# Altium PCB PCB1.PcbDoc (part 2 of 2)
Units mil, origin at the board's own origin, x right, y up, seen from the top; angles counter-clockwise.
Board outline 3937.01 x 3937.01 mil, 4 copper layers (Top Layer, Layer 1, Layer 2, Bottom Layer), stack 68.734 mil thick; 96 components, 71 nets, 353 pads, 281 vias.
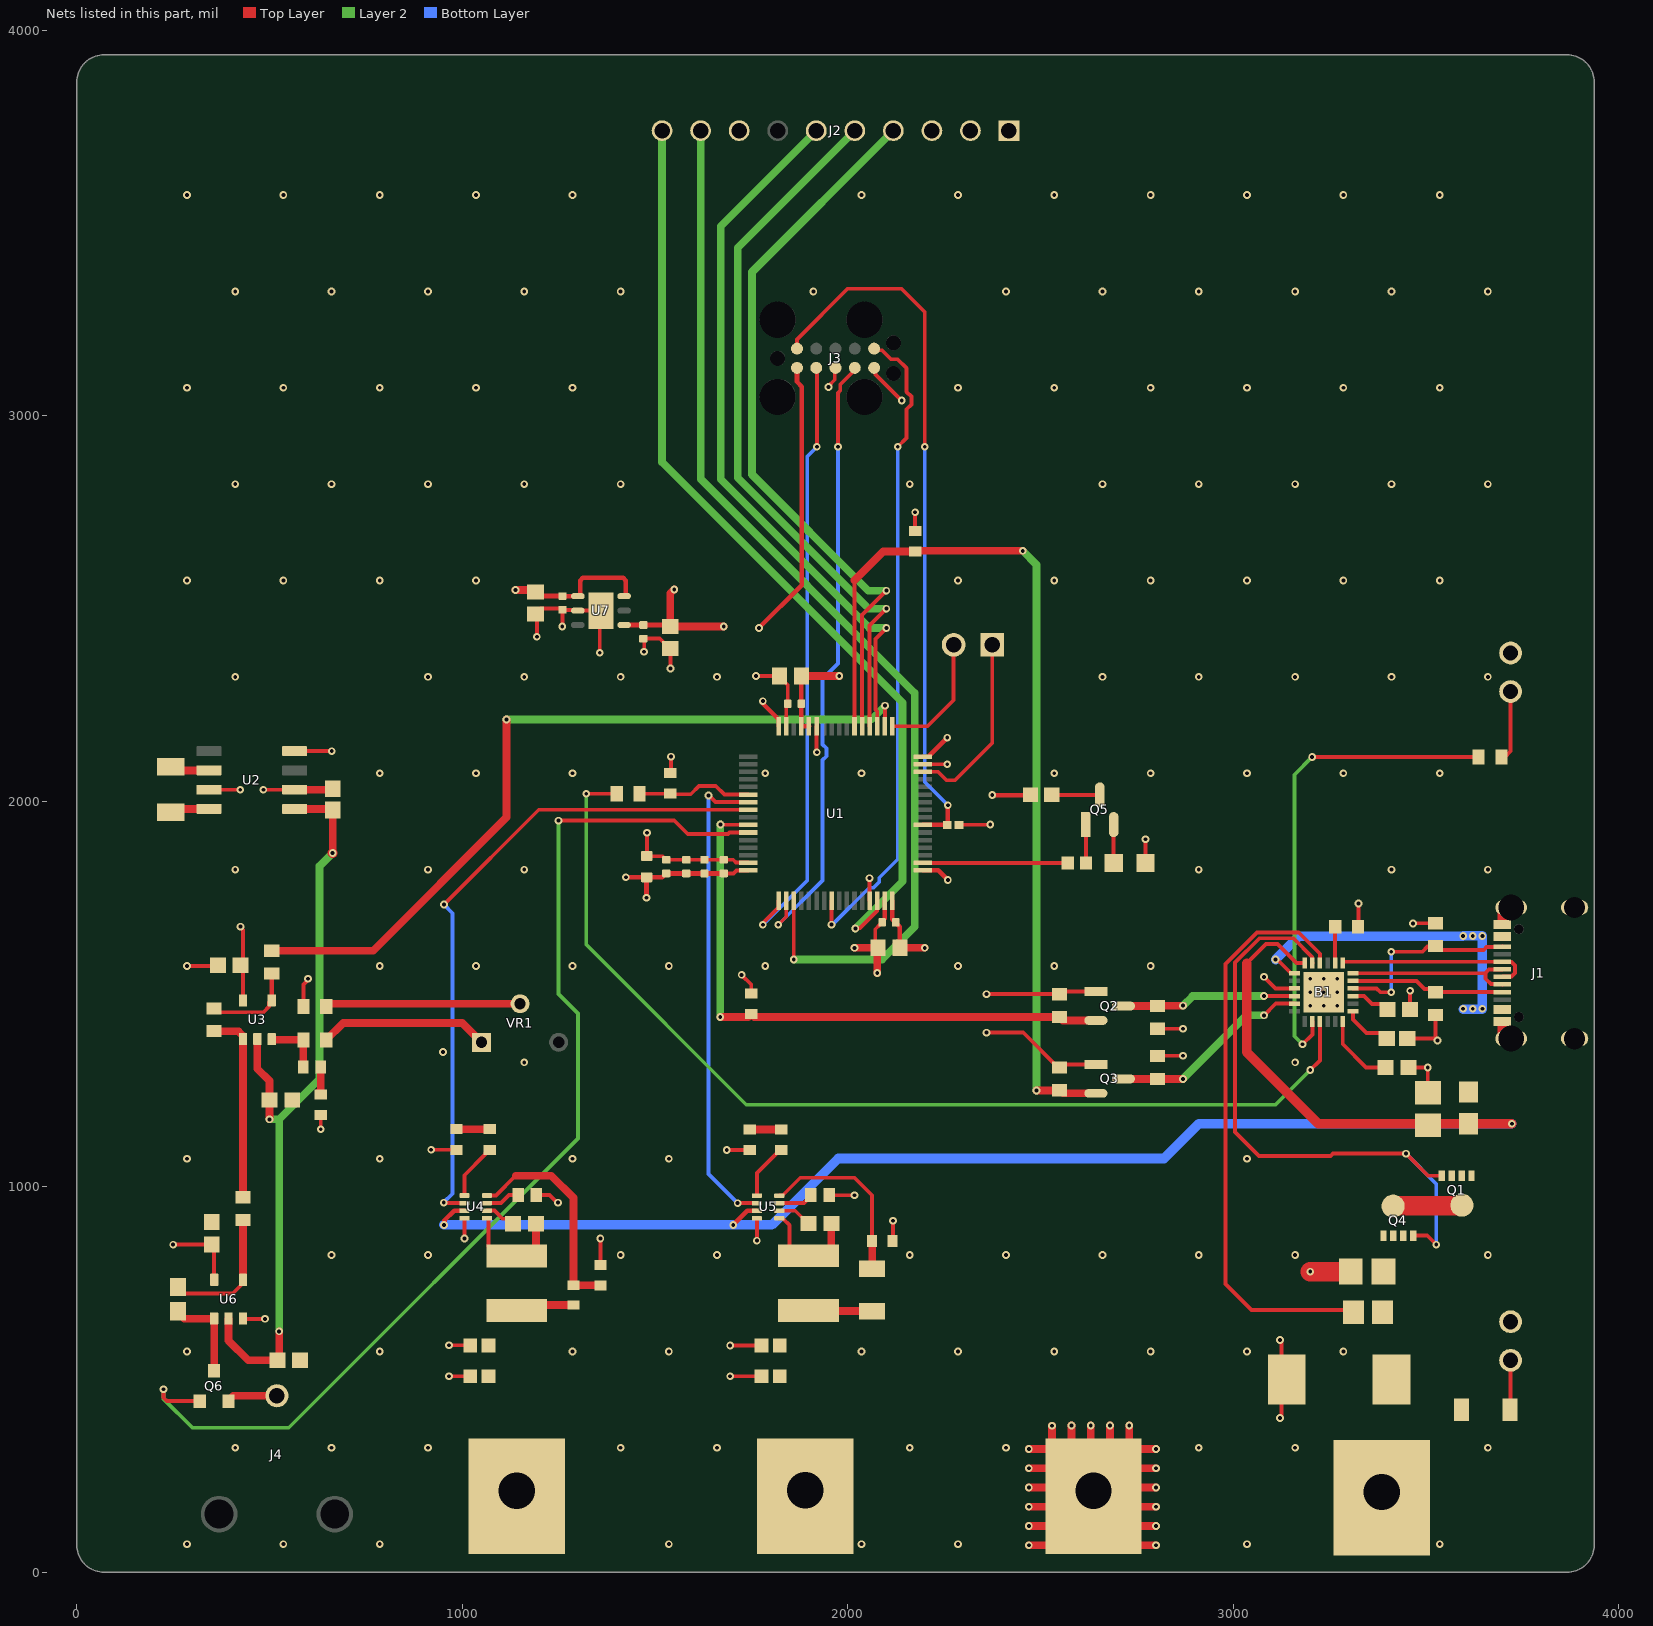
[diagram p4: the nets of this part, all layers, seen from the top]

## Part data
B1: library part CMP-019-00051-3, "USB, Type-C Controller PMIC W-QFN4040-24 (Type A1)", Manufacturer_Name="Diodes Incorporated", Manufacturer_Part_Number=AP33772SDKZ-13-FA01, Mouser Part Number=621-P33772SDKZ13FA01
C1 C4 C17 C19 C22 C23 C24 C27: library part CMP-2006-02299-1, "C0603C104K4RAC7013", Manufacturer=Kemet
C2 C14 C30 C33: library part CMP-001-00004-6, "Chip Capacitor, 1 uF, +/- 10%, 16 V, 0603 (1608 Metric)", Capacitor Type=Ceramic, Case/Package=0603, Max Operating Temperature=125°C, Min Operating Temperature=-55°C, Tolerance=10%, Voltage Rating=16V
C3 C8 C9 C10 C11 C13 C31 C32: library part CMP-001-00061-3, "Chip Capacitor, 100nF +/-20%, 10V, 0402, Thickness 0.6 mm", Case/Package=0402, Max Operating Temperature=85°C, Min Operating Temperature=-55°C, Tolerance=20%, Voltage Rating=10V
C5: library part CMP-03422-000857-1, "CC0603MRX5R8BB105 / CAP CER 1UF 25V X5R 0603", Capacitance="1 uF", Manufacturer=YAGEO, Manufacturer Part Number=CC0603MRX5R8BB105, Package=CC0603-DA, Temperature="-55°C to +125°C", Temperature Characteristic=X5R, Temperature Coefficient=15%, Temperature Range High=+125°C, Temperature Range Low=-55°C, Tolerance=0.2, Voltage="25 V"
C6: library part CMP-001-00001-6, "Chip Capacitor, 0.1 uF, +/- 5%, 16 V, 0402 (1005 Metric)", Capacitor Type=Ceramic, Case/Package=0402, Max Operating Temperature=125°C, Min Operating Temperature=-55°C, Tolerance=5%, Voltage Rating=16V
C7: library part CMP-001-00076-4, "Chip Capacitor, 4.7µF +/-20%, 10V, 0603, Thickness 1 mm", Case/Package=0603, Max Operating Temperature=85°C, Min Operating Temperature=-55°C, Tolerance=10%, Voltage Rating=10V
C12 C15: library part CMP-2000-06047-2, "C3216X7R1V106K160AC / Multilayer Ceramic Capacitors 10uF ±10% 35V X7R SMD 1206", Case Code (Imperial)=1206, Case Code (Metric)=3216, Dielectric=X7R, Dielectric Material=Ceramic, Max Operating Temperature=125°C, Min Operating Temperature=-55°C, Package Quantity=2000, Tolerance=10%, Voltage Rating=35V
C16: library part CMP-1037-05002-1, "CAP 47uF 10V ±20% 1206 (3216 Metric) Thickness 1.9mm SMD", Case-EIA=1206, Case-Metric=3216, Rated Voltage="10 V", Tolerance=Â±20%
C18: library part CMP-06035-020296-1, "Chip Multilayer Ceramic Capacitors for General Purpose, 0603, 10uF, X7R, 15%, 10%, 10V / GRM188Z71A106KA73J"
C20 C21: library part CMP-03020-034693-1, "C0603C333J4REC7411 / CAP CER 0603 33NF 16V X7R 5%", Case/Package=0603, Max Operating Temperature=125°C, Min Operating Temperature=-55°C, Tolerance=5%, Voltage Rating=16V
C25 C26 C28 C29: library part CMP-2000-06337-3, "GRM188R61A226ME15D / Chip Multilayer Ceramic Capacitors for General Purpose, 0603, 22uF, X5R, 15%, 20%, 10V", Case Code (Imperial)=0603, Case Code (Metric)=1608, Dielectric=X5R, Max Operating Temperature=85°C, Min Operating Temperature=-55°C, Package Quantity=4000, Tolerance=20%, Voltage Rating=10V
D1: library part CMP-004-00031-2, "151051BS04000 / Single Color LED, Blue, Diffused, T-1 3/4, 4.9mm", Case/Package=Radial, Color=Blue, Forward Current=100mA, Forward Voltage=3.2V, Max Operating Temperature=85°C, Max Reverse Voltage (DC)=5V, Min Operating Temperature=-40°C, Test Current=20mA
D2: library part CMP-007-00039-1, "151051RS11000 / WL-TMRC Red Color Diffused 5 mm Round Through Hole LED", Case/Package=Radial, Forward Current=100mA, Forward Voltage=2.1V, Max Operating Temperature=85°C, Min Operating Temperature=-40°C
D3: library part CMP-2000-05906-2, "DIODE SCHOTTKY 50V 5A SMC", Average Rectified Current=5A, Capacitance=300pF, Case/Package=SMC, Forward Voltage=700mV, Max Forward Surge Current (Ifsm)=100A, Max Operating Temperature=125°C, Max Repetitive Reverse Voltage (Vrrm)=50V, Min Operating Temperature=-55°C, Package Quantity=3000, Peak Reverse Current=500uA
D4: library part CMP-2000-06620-1, "Ultra Bright AlInGaP Chip LED, 75 mW, -55 to 85 degC, 2-Pin SMD (0805), RoHS, Tape and Reel", Emitting Color=YellowGreen, Forward Current=30mA, Forward Voltage=2.4V, Manufacturer=Lite-On, Operating Temp Range=-55Cto85C, Operating Temperature Classification=Industrial, Package Description="2-Pin Surface Mounted Device, Body 2 x 1.25 mm", Package Reference=LTST-C170KGKT-2, Package Type=ChipLed, Power Dissipation=75W, Power Dissipation Max=75mW, Reverse Voltage=5V, Test Current (It)=20mA
J1: library part CMP-245163-000001-1, "CONN RCPT USB2.0 TYPEC 5A", Current Rating=5/6.25/1.25/0.25A, Manufacturer=GCT, Package=0, Temperature="-40°C to +85°C", Temperature Range High=+85°C, Temperature Range Low=-40°C, Voltage Rating=20V
J2: library part CMP-039-000000-3, "Samtec Connector .1\" pitch, long ahh pins", Package=None
J3: library part CMP-035-000000-1, "Cbl Plug-Of-Nails 10-Pin w/Legs", Package=None
J4: library part CMP-002-00084-4, "JACK, BNC, 50OHM, R/A, THT; Connector Type: BNC Coaxial; Body Style: Right Angle J", Case/Package=None
J5 J6 J7 J8: library part CMP-002-00082-3, "Banana Test Connector, 4mm, Jack, Panel Mount, 15 A, 7 kV, Tin Plated Contacts, Red", Max Current Rating=15A, Max Operating Temperature=85°C, Min Operating Temperature=-55°C, Voltage Rating=3.5kV
J9: library part CMP-15831-000009-1, "CONN HEADER VERT 2POS 2.54MM", Current Rating=3A, Manufacturer=Harwin, Temperature="-40°C to +105°C", Temperature Range High=+105°C, Temperature Range Low=-40°C
L1 L2: library part CMP-14484-001090-1, "NRS5040T3R3NMGJ / SMD Power Inductors 3.3uH ±30% 3.3A 35.1mΩ", Case/Package=Nonstandard, Current Rating=3.3A, DC Resistance (DCR)=27mR, Max Operating Temperature=120°C, Min Operating Temperature=-25°C, Resistor Type=Wirewound, Saturation Current=4A, Self Resonant Frequency=32MHz, Test Frequency=100kHz, Tolerance=30%
Q1 Q4: library part CMP-12801-000078-1, "MOSFET N-CH 60V 13A POWERDI", Capacitance=2.09E-09F, Continuous Drain Current (ID)=30A, Drain to Source Breakdown Voltage=60V, Drain to Source Resistance=7.8mR, Gate to Source Voltage (Vgs)=20V, Input Capacitance=2.09nF, Max Operating Temperature=150°C, Max Power Dissipation=2.2W, Min Operating Temperature=-55°C, Package Quantity=2000
Q2 Q3: library part CMP-07173-000101-1, "MOSFET N-CH 50V 220MA SOT-23", Case/Package=SOT-23, Continuous Drain Current (ID)=220mA, Drain to Source Breakdown Voltage=50V, Drain to Source Resistance=3.5R, Gate to Source Voltage (Vgs)=20V, Input Capacitance=27pF, Max Operating Temperature=150°C, Max Power Dissipation=360mW, Min Operating Temperature=-55°C, On-State Resistance=6R, Package Quantity=1, Threshold Voltage=1.3V
Q5: library part CMP-2000-04931-2, "TRANS NPN 40V 0.2A SMD SOT23-3", Case/Package=SOT-23, Collector Base Voltage (VCBO)=60V, Collector Emitter Breakdown Voltage=40V, Collector Emitter Saturation Voltage=300mV, Continuous Collector Current=200mA, Emitter Base Voltage (VEBO)=6V, Frequency=300MHz, Max Operating Temperature=150°C, Max Power Dissipation=300mW, Min Operating Temperature=-55°C, Package Quantity=3000, Power Dissipation=350mW
Q6: library part CMP-1048-00772-1, "General Purpose Transistor, NPN Silicon, 3-Pin SOT-23, Pb-Free, Tape and Reel", Manufacturer="On Semiconductor"
R1 R2 R4 R5 R7 R8 R10: library part CMP-2000-04091-1, "RC0603FR-075K1L", Manufacturer=Yageo
R3 R13 R14 R15 R16 R23: library part CMP-009-00014-5, "Chip Resistor, 1 KOhm, +/-1%, 0.1 W, -55 to 155 degC, 0603 (1608 Metric)", Case/Package=0603, Max Operating Temperature=155°C, Min Operating Temperature=-55°C, Power=100mW, Tolerance=1%, Voltage Rating=50V
R6: library part CMP-06022-000566-1, "NCG18XH103F0SRB / NTC Thermistor 10kΩ 1% SMD  0201 (0603 Metric)", Case/Package=0603, Max Operating Temperature=150°C, Min Operating Temperature=-55°C, Tolerance=1%
R9 R18 R19 R20 R21 R22 R24 R27 R32 R33: library part CMP-2100-03664-2, "RC0603FR-0710KL / RES 10K OHM 1% 1/10W 0603", Case Code (Imperial)=0603, Case Code (Metric)=1608, Max Operating Temperature=155°C, Max Power Dissipation=100mW, Min Operating Temperature=-55°C, Resistance=10kR, Resistance Tolerance=1%, Resistor Type="Thick Film", Temperature Coefficient=100ppm/°C, Voltage Rating=75V, Voltage Rating (DC)=50V
R11: library part CMP-009-00179-1, "5 mOhms Â±1% 0.5W, 1/2W Chip Resistor 0805 (2012 Metric) Automotive AEC-Q200, Current Sense Thick Film", Case/Package="2012-2 Panasonic"
R12: library part CMP-2001-00580-1, "ERA6AEB101V", Manufacturer=Panasonic
R17: library part CMP-2000-03826-1, "CRCW0603100RFKTA", Manufacturer="Vishay Dale"
R25: library part CMP-03412-001731-1, "RT1206BRD075KL / RES SMD 5K OHM 0.1% 1/4W 1206", Manufacturer=Yageo, Manufacturer Part Number=RT1206BRD075KL, Package=RT1206-0.65, Power Rating=0.25W, Resistance=5kΩ, Temperature="-55°C to +155°C", Temperature Coefficient=25ppm/°C, Temperature Range High=+155°C, Temperature Range Low=-55°C, Tolerance=0.1%, Voltage Rating=200V
R26: library part CMP-250906-096381-1, "RES Thin Film, 31.2kΩ, 0.1%, 0.25W, 50ppm/°C, 1206"
R28: library part CMP-26527-007404-1, "RMCF0603JG3K00 / 3kΩ ±5% 0.1W 0603 Thick Film Chip Resistor AEC-Q200 compliant", Case/Package=0603, Max Operating Temperature=155°C, Max Power Dissipation=100mW, Min Operating Temperature=-55°C, Resistance=3kR, Resistor Type="Thick Film", Temperature Coefficient=200ppm/°C, Tolerance=5%
R29: library part CMP-1012-00705-2, "RC0603FR-0752K3L", Manufacturer=Yageo
R30: library part CMP-26527-005064-1, "RMCF0603JG510R / 510Ω ±5% 0.1W 0603 Thick Film Chip Resistor AEC-Q200 compliant", Case/Package=0603, Max Operating Temperature=155°C, Max Power Dissipation=100mW, Min Operating Temperature=-55°C, Package Quantity=10000, Resistor Type="Thick Film", Temperature Coefficient=200ppm/°C, Tolerance=5%
R31: library part CMP-26527-003372-1, "RMCF0603FG2K00 / 2kΩ ±1% 0.1W 0603 Thick Film Chip Resistor AEC-Q200 compliant", Case/Package=0603, Max Operating Temperature=155°C, Min Operating Temperature=-55°C, Resistance=2kR, Resistor Type="Thick Film", Temperature Coefficient=100ppm/°C, Tolerance=1%
U1: library part CMP-12105-000051-1, "MAINSTREAM ARM CORTEX-M4 CORE WI", Ambient Temperature Range High=+85°C, Ambient Temperature Range Low=-40°C, Frequency=170MHz, Manufacturer=STMicroelectronics, Max Junction Temp=+105°C, Max Supply Voltage=3.6V, Min Supply Voltage=1.71V, Package=LQFP64-5W, Temperature="-40°C to +105°C"
U2: library part CMP-0065-00039-3, "Switched Capacitor Voltage Converter, 8-pin Narrow SOIC, Pb-Free", Manufacturer="Texas Instruments", PackageTopMarking=NSZXTT*LM26*63M, PowerWise=N
U3 U6: library part CMP-0272-04163-2, "Precision, Rail-to-Rail Input/Output, Low Offset Voltage, Low Input Bias Current Op Amp with E-trim, 4.5 to 36 V, -40 to 125 degC, 5-Pin SOT-23 (DBV), Green (RoHS & no Sb/Br), Tape and Reel", Temperature Max="125 degC", Temperature Min="-40 degC"
U4 U5: library part CMP-04918-000610-1, "3.8-V to 30-V, 3-A, 200-kHz to 2.2-MHz, low-IQ synchronous buck converter in SOT-583 package 8-SOT-5X3 -40 to 150"
U7: library part CMP-019-00050-2, "500 mA low quiescent current low noise voltage regulator", Case/Package="DFN EP", Dropout Voltage=400mV, Max Operating Temperature=125°C, Max Supply Voltage=5.5V, Min Operating Temperature=-40°C, Output Current=500mA, Output Voltage=3.3V
VR1: library part CMP-1747-00004-1, "Square Trimpot(R) Trimming Potentiometer, 10 KOhm, 300 V, -55 to 125 degC, 3-Pin THD, RoHS, Tube", Case Code (Imperial)=0612, Case Code (Metric)=1632, Case/Package=1206, Max Operating Temperature=125degC, Min Operating Temperature=-25degC, Package Quantity=5000, Power Rating="1 W", Resistance="50 mohm", Tolerance=1%, Voltage Rating="220 mV"

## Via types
v1: diameter 20, hole 10, Top Layer to Bottom Layer, 277 vias
v2: diameter 118.11, hole 94.49, Top Layer to Bottom Layer, 4 vias

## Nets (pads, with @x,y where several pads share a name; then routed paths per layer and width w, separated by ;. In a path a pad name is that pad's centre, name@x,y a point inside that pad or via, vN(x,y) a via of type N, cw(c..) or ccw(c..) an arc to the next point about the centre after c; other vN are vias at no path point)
3V3: C2.2 C3.2 C7.2 C8.2 C9.2 C10.2 C11.2 C13.2 C14.2 C32.2 C33.2 J3.1 Q2.1 Q3.1 R4.2 R8.2 R30.2 R32.1 R33.1 U1.1 U1.16 U1.28 U1.29 U1.32 U1.48 U1.64 U7.4 | length 2962.2
  Top Layer w10: C11.2@1678.5,1812.99 1704.09,1812.99 1711.68,1820.58 1741.83,1820.58 U1.48@1742.13,1820.87 ; v1(1725,1550) 1750,1525 R33.1@1750,1501.64 ; R32.1@2175,2701.64 v1(2175,2750) ; v1(2360,1400) 2455.59,1400 2546.06,1309.53 R8.2@2550,1309.53 ; v1(2360,1500) 2549.53,1500 R4.2@2550,1499.53 2556.93,1506.46 Q2.1@2643.85,1506.46 ; R8.2@2551.57,1309.53 2559.44,1317.4 Q3.1@2643.85,1317.4
  Top Layer w12: U7.4@1416.1,2457.6 1469.88,2457.6 C32.2@1470,2457.72 1535.83,2457.72 C33.2@1540,2453.54 ; v1(1424.48,1803.15) C7.2@1478.51,1803.15 ; v1(1477.87,1750) 1478.19,1750.32 1478.19,1802.83 C7.2@1478.51,1803.15 ; C11.2@1678.5,1812.99 C10.2@1628.5,1812.99 C9.2@1581.34,1812.99 C8.2@1529.49,1812.99 1528.5,1812.99 1518.66,1803.15 C7.2@1478.51,1803.15 ; v1(1770,2450) 1881.25,2561.25 1881.25,3075.6 1868.5,3088.35 J3.1@1868.5,3115 ; v1(1780,2260) 1781.53,2258.47 1781.53,2251.75 1820.87,2212.41 U1.32@1820.87,2194.88 ; U1.29@1879.83,2194.79 U1.29@1879.92,2194.88 ; C2.2@1879.92,2325.49 C3.2@1879.92,2253.38 U1.29@1879.92,2194.88 ; U1.28@1899.61,2194.88 U1.29@1879.92,2194.88 ; U1.64@2116.14,1742.13 2116.14,1694.65 C13.2@2124.73,1686.06 2124.73,1685.08 2135.56,1674.25 C14.2@2135.56,1620 ; U1.1@2194.88,1820.87 2235.39,1820.87 v1(2260,1796.26) ; U1.16@2194.88,2116.14 2212.41,2116.14 2212.5,2116.24 2212.5,2119.35 v1(2258.5,2165.35) ; v1(2375,2016.36) 2473.67,2016.36 R30.2@2474.11,2016.8
  Top Layer w20: v1(1550,2550) 1540,2540 C33.2@1540,2453.54 1678.19,2453.54 v1(1678.35,2453.7) ; C2.2@1879.92,2325.49 v1(1978.19,2325.49) ; C14.2@2135.56,1620 v1(2200,1620)
3VO_JACK: C26.1 C29.1 J5.1 L1.2 R26.2 | length 165.9
  Top Layer w20: L1.2@1898.58,679.22 1899.69,678.12 2062.44,678.12 R26.2@2063.54,677.02
  other v2: 1889.76,212.27
5VO: C25.1 C28.1 J6.1 L2.2 R29.2 | length 152.2
  Top Layer w20: L2.2@1142.24,679.71 1155.94,693.41 R29.2@1288.73,693.41
  other v2: 1141.73,211.85
5VO_EN: U1.40 U4.2 | length 1738
  Top Layer w10: v1(951.88,959) 952.46,958.42 1005.02,958.42 U4.2@1005.6,957.84 ; v1(952.46,1732.28) 1198.52,1978.35 U1.40@1742.13,1978.35
  Bottom Layer w10: v1(951.88,959) 975,982.12 975,1709.74 v1(952.46,1732.28)
+5: C17.2 C19.2 C30.2 C31.2 J2.02 R5.2 R7.2 R18.1 U2.8 U3.5 U6.5 U7.1 U7.6 | length 1029.4
  Top Layer w10: v1(250,850) C19.2@350,850 356.3,843.7 U6.5@356.3,758.86 ; v1(425,1675) 425,1672.29 431.1,1666.19 U3.5@431.1,1483.74 ; U2.8@565.36,2130.35 v1(661.55,2130.35) ; v1(632.79,1149.41) R18.1@632.79,1186.9 ; R7.2@2803.85,1339.06 2804.8,1340 v1(2870,1340) ; R5.2@2803.85,1410 v1(2870,1410)
  Top Layer w12: C30.2@1193.56,2548.27 1193.56,2544.81 1205.65,2532.72 C31.2@1260,2532.72 ; C31.2@1260.32,2532.4 U7.1@1299.96,2532.4 1304.09,2532.4 1305.82,2534.13 1305.82,2572.93 1312.85,2579.96 1417.45,2579.96 1424.48,2572.93 1424.48,2538.02 U7.6@1425.06,2537.44
  Top Layer w20: v1(1138.19,2548.27) C30.2@1193.56,2548.27
-5: C18.1 C24.2 C27.2 U2.5 U3.2 U6.2 | length 2037.8
  Top Layer w10: U3.2@468.5,1378.42 U3.2@468.5,1383.34
  Top Layer w20: U6.2@393.7,657.48 393.7,601.1 444.8,550 C27.2@520.47,550 525,554.53 v1(525,625) ; U3.2@468.5,1378.42 468.5,1306.5 500,1275 C24.2@500,1225 v1(500,1175) ; U2.5@565.36,1980.35 C18.1@661.55,1980.35 ; v1@664.14,1866.56 C18.1@664.14,1977.77
  Top Layer w25.59: C18.1@661.55,1980.35 C18.1@664.14,1977.77 ; v1(663.72,1866.14) v1@664.14,1866.56
  Layer 2 w20: v1(500,1175) 525,1175 ; v1(525,625) 525,1175 ; v1(663.72,1866.14) 629.96,1832.38 629.96,1279.96 525,1175
BST: C23.1 U4.6 | length 82.9
  Top Layer w10: U4.6@1063.95,938.29 1083.46,938.29 1104.4,917.35 1119.37,917.35 C23.1@1132.67,904.04
CC1: B1.17 J1.A5 R2.2 | length 399.9
  Top Layer w10: B1.17@3310.94,1534.37 3475.63,1534.37 3496.83,1513.17 3517.31,1513.17 3525.16,1505.31 J1.A5@3698.82,1505.31
CC2: B1.16 J1.B5 R1.2 | length 510.3
  Top Layer w10: B1.16@3310.94,1514.69 3372.14,1514.69 3381.98,1504.84 v1(3410.16,1504.84) ; v1(3410.16,1609.84) 3491.17,1609.84 3504.75,1623.43 R1.2@3525.16,1623.43 ; R1.2@3525.16,1624.84 3535.16,1614.84 3650.16,1614.84 3657.83,1622.52 3697.91,1622.52 J1.B5@3698.82,1623.43
  Bottom Layer w10: v1(3410.16,1504.84) v1(3410.16,1609.84)
D+: B1.19 J1.A6 J1.B6 | length 510.7
  Top Layer w10: B1.19@3284.37,1580.63 3284.37,1583.15 3285.28,1584.06 J1.B6@3698.82,1584.06 3699.73,1583.15 3722.73,1583.15 3731.46,1574.42 3731.46,1554.32 3722.73,1545.59 3699.73,1545.59 J1.A6@3698.82,1544.69
D-: B1.18 J1.A7 J1.B7 | length 456.8
  Top Layer w10: B1.18@3310.94,1554.06 3655.13,1554.06 ; J1.B7@3698.82,1525 3697.91,1525.91 3669.17,1525.91 3655.13,1539.95 3655.13,1555.22 3663.38,1563.47 3697.91,1563.47 J1.A7@3698.82,1564.37
DAC1_OUT1: R13.2 U1.18 | length 2057
  Top Layer w10: U1.18@2096.46,2194.88 2096.77,2195.2 2096.77,2248.06 v1(2097.09,2248.38)
  Top Layer w20: R13.2@505.91,1612.6 768.95,1612.6 1114.86,1958.51 v1(1114.86,2212.41)
  Layer 2 w20: v1(1114.86,2212.41) 2060.22,2212.41 2061.28,2213.47 2062.18,2213.47 v1(2097.09,2248.38)
GND: B1.3 B1.25 C1.2 C2.1 C3.1 C4.1 C5.2 C6.1 C7.1 C8.1 C9.1 C10.1 C11.1 C12.2 C13.1 C14.1 C15.2 C17.1 C18.2 C19.1 C20.2 C21.2 C24.1 C25.2 C26.2 C27.1 C28.2 C29.2 C30.1 C31.1 C32.1 C33.1 D1.2 D2.2 D3.2 D4.1 J1.1 J1.2 J1.3 J1.4 J1.A1-B12 J1.B1-A12 J2.01 J2.03 J2.08 J3.3 J3.5 J7.1 R1.1 R2.1 R6.1 R9.2 R14.2 R19.2 R21.2 R24.2 R27.2 U1.15 U1.27 U1.31 U1.47 U1.61 U1.63 U2.3 U2.6 U4.4 U5.4 U6.3 U7.2 U7.7 | length 5409.8
  Top Layer w10: v1(286,1573) 363.95,1573 C17.1@365.95,1575 ; U2.3@342.92,2030.35 v1(424.14,2030.35) ; U6.3@431.1,657.48 v1(488.19,657.48) ; v1(484.14,2030.35) U2.6@565.36,2030.35 ; R14.2@588.15,1467.99 588.15,1525.24 599.96,1537.06 v1(599.96,1539.76) ; v1(919.35,1096.13) R19.2@985.35,1096.13 ; v1(965.66,508.59) C28.2@1020.77,508.59 ; v1(965.66,589) 1020.36,589 C25.2@1020.77,588.59 ; v1(1005.69,865.99) U4.4@1005.69,918.61 ; C20.2@1192.35,979 1226.31,979 1246.31,959 v1(1248.73,959) ; v1(1193.56,2427.21) 1193.56,2491.18 1202.42,2500.04 C31.1@1259.84,2500.04 ; v1(1259.69,2453.54) 1259.84,2453.7 C31.1@1259.84,2497.97 ; C31.1@1260,2497.28 1261.18,2496.1 U7.2@1299.96,2496.1 ; U7.2@1299.96,2495 U7.7@1360,2495 1356.83,2491.83 v1(1356.83,2385.5) ; v1(1358.32,865.99) 1358.32,798.06 R27.2@1358.73,797.64 ; C32.1@1470,2422.28 C32.1@1472.11,2422.28 ; v1(1471.65,2388.39) 1472.11,2388.84 C32.1@1472.11,2422.28 ; v1(1479.25,1918.54) 1479.25,1859.02 C7.1@1478.51,1858.27 1479.25,1857.53 1519.4,1857.53 1528.5,1848.43 C8.1@1529.49,1848.43 C9.1@1581.34,1848.43 C10.1@1628.5,1848.43 C11.1@1678.5,1848.43 1703.11,1848.43 1710.08,1841.46 1741.22,1841.46 U1.47@1742.13,1840.55 ; R9.2@1540,2073.28 1541.38,2074.66 v1(1541.38,2116.14) ; C33.1@1540,2396.46 1538.03,2396.46 1523.35,2411.14 1523.35,2411.43 1512.49,2422.28 C32.1@1472.11,2422.28 ; v1(1540.55,2345) C33.1@1540.55,2404.25 ; v1(1686.34,1095.4) R21.2@1746.34,1095.4 ; v1(1695,508.59) 1776.19,508.59 C29.2@1776.43,508.36 ; v1(1695,588.59) 1776.19,588.59 C26.2@1776.43,588.36 ; v1(1762.13,2325.49) C2.1@1822.84,2325.49 ; v1(1764.41,860.41) U5.4@1764.41,918.24 ; C2.1@1822.84,2323.53 1844.49,2301.87 C3.1@1844.49,2253.38 1840.55,2249.44 U1.31@1840.55,2194.88 ; U1.27@1919.29,2194.88 1919.29,2128.18 v1(1920,2127.47) ; v1(1950,3075) 1950,3077.56 1966.4,3093.96 1966.4,3114.91 1968.5,3117.01 J3.3@1968.5,3124.61 ; C21.2@1951.75,978.76 1952.23,978.28 v1(2017.72,978.28) ; v1(2056.77,1800.89) 2056.93,1800.73 2056.93,1742.28 U1.61@2057.09,1742.13 ; J3.5@2068.5,3124.61 2072.52,3120.59 2072.52,3107.48 2140,3040 v1(2140.25,3040) ; C14.1@2076.77,1618.3 C14.1@2078.47,1620 2071.58,1626.89 2071.58,1668.35 2083.47,1680.24 2084.45,1680.24 2089.3,1685.08 C13.1@2089.3,1686.06 ; R24.2@2116.83,859.51 2117.33,860.02 2117.33,911.47 v1(2117.84,911.98) ; U1.15@2194.88,2096.46 v1(2258.5,2096.46) ; C6.1@2289.21,1938.98 2289.72,1939.49 2369.49,1939.49 v1(2370,1940) ; v1(2772.49,1901.66) 2772.49,1840.2 D4.1@2772.79,1839.89 ; v1(3080.16,1544.84) 3110.32,1514.69 B1.3@3159.37,1514.69 ; v1(3121.69,400.37) 3121.69,403.08 3125.82,407.21 3125.82,486.65 D3.2@3139.17,500 3125.82,513.35 3125.82,595.7 3121.69,599.83 v1(3121.69,602.54) ; v1(3235.16,1504.84) v1(3235.16,1539.84) ; C5.2@3324.21,1674.84 3325.16,1675.79 v1(3325.16,1734.84) ; R6.1@3451.77,1384.84 v1@3525.16,1384.84 ; C1.2@3454.68,1309.84 v1(3505.16,1309.84) C12.2@3505.16,1244.58 ; C4.1@3459.21,1459.84 v1(3459.21,1508.9) ; v1(3466.98,1683.4) 3467.48,1683.9 R1.1@3525.16,1683.9 ; R2.1@3525.16,1445.79 v1@3525.16,1384.84 ; v1(3530.16,1379.84) v1@3525.16,1384.84 ; J1.1@3698.82,1398.02 3712.39,1384.45 J1.1@3721.46,1384.45 ; J1.2@3698.82,1711.04 3712.39,1724.61 J1.2@3721.46,1724.61
  Top Layer w12: C13.1@2089.3,1686.06 2089.3,1689.11 2096.46,1696.27 U1.63@2096.46,1742.13
  Top Layer w20: U2.6@565.36,2030.35 C18.2@671.03,2030.35 ; v1(2017.72,1620) C14.1@2078.47,1620 ; v1(2076.77,1555) C14.1@2076.77,1618.3 ; v1(2470,70) J7.1@2517.21,70 ; v1(2470,120) J7.1@2517.21,120 ; v1(2470,170) J7.1@2517.21,170 ; v1(2470,220) J7.1@2517.21,220 ; v1(2470,270) J7.1@2517.21,270 ; v1(2470,320) J7.1@2517.21,320 ; v1(2530,380) 2530,304.65 2637.8,196.85 2637.8,205 J7.1@2752.8,320 ; J7.1@2580.6,305.49 v1(2580.6,380.84) ; J7.1@2630.6,305.49 v1(2630.6,380.84) ; J7.1@2680.6,305.49 v1(2680.6,380.84) ; J7.1@2730.6,305.49 v1(2730.6,380.84) ; J7.1@2734.44,301.65 J7.1@2752.8,320 ; J7.1@2752.8,70 v1(2800,70) ; J7.1@2752.8,120 v1(2800,120) ; J7.1@2752.8,170 v1(2800,170) ; J7.1@2752.8,220 v1(2800,220) ; J7.1@2752.8,270 v1(2800,270) ; v1(2800,320) J7.1@2752.8,320
  Top Layer w25: J1.1@3698.82,1398.02 3698.82,1414.39 ; J1.B1-A12@3698.82,1691.18 J1.2@3698.82,1711.04
  Top Layer w50: v1(3200.2,780.03) C15.2@3305.47,780.03
  other v1: 286,73 536,73 786,73 1536,73 2036,73 2286,73 3036,73 3536,73 411,323 661,323 911,323 1411,323 1661,323 2161,323 2411,323 2911,323 3161,323 3661,323 286,573 786,573 1286,573 1536,573 2036,573 2286,573 2536,573 2786,573 3036,573 3286,573 661,823 911,823 1411,823 1661,823 2161,823 2411,823 2661,823 2911,823 3161,823 3661,823 286,1073 786,1073 1286,1073 1536,1073 3036,1073 1161,1323 3161,1323 950,1350 3200.16,1469.84 3235.16,1469.84 3270.16,1469.84 3200.16,1504.84 3270.16,1504.84 3200.16,1539.84 3270.16,1539.84 786,1573 1036,1573 1286,1573 1536,1573 1786,1573 2286,1573 2536,1573 2786,1573 411,1823 911,1823 1161,1823 2911,1823 3411,1823 3661,1823 786,2073 1036,2073 1286,2073 1786,2073 2036,2073 2536,2073 2786,2073 3036,2073 3286,2073 3536,2073 411,2323 911,2323 1161,2323 1411,2323 1661,2323 2661,2323 2911,2323 3161,2323 3411,2323 3661,2323 286,2573 536,2573 786,2573 1036,2573 2286,2573 2536,2573 2786,2573 3036,2573 3286,2573 3536,2573 411,2823 661,2823 911,2823 1161,2823 1411,2823 2161,2823 2661,2823 2911,2823 3161,2823 3411,2823 3661,2823 286,3073 536,3073 786,3073 1036,3073 1286,3073 2286,3073 2536,3073 2786,3073 3036,3073 3286,3073 3536,3073 411,3323 661,3323 911,3323 1161,3323 1411,3323 1911,3323 2411,3323 2661,3323 2911,3323 3161,3323 3411,3323 3661,3323 286,3573 536,3573 786,3573 1036,3573 1286,3573 2036,3573 2286,3573 2536,3573 2786,3573 3036,3573 3286,3573 3536,3573
  other v2: 2637.8,211.85
I2C1_SCL: J2.09 U1.51 | length 2795.2
  Top Layer w10: v1(1860,1590) 1860.12,1590.12 U1.51@1860.12,1740.43
  Layer 2 w20: J2.09@1618.5,3740.16 1618.5,2836.5 2173.94,2281.06 2173.94,1674.47 2089.47,1590 v1(1860,1590)
I2C1_SDA: J2.10 U1.62 | length 2480.8
  Top Layer w10: v1(2020,1670) 2021.91,1671.91 2031.91,1671.91 2075.87,1715.87 2075.87,1741.22 U1.62@2076.77,1742.13
  Layer 2 w20: J2.10@1518.5,3740.16 1518.5,2880.09 2142.45,2256.15 2142.45,1792.45 v1(2020,1670)
I2C2_SCL: Q3.2 R8.1 R32.2 U1.22 | length 2417.1
  Top Layer w10: U1.22@2017.72,2194.88 2017.72,2574.1 ; R8.1@2549.53,1250 R8.1@2550,1250.47 ; R8.1@2551.57,1250.47 R8.1@2559.44,1242.6
  Top Layer w20: 2017.72,2574.1 2091.98,2648.36 R32.2@2175,2648.36 ; R32.2@2175,2650 v1(2454.3,2650) ; v1(2490,1250) R8.1@2549.53,1250 ; R8.1@2559.44,1242.6 Q3.2@2643.85,1242.6
  Layer 2 w20: v1(2454.3,2650) 2490,2614.3 v1(2490,1250)
I2C2_SDA: Q2.2 R4.1 R33.2 U1.42 | length 1551.5
  Top Layer w10: v1(1670,1940) 1670.51,1939.49 1741.61,1939.49 U1.42@1742.13,1938.98 ; R4.1@2550,1440.47 R4.1@2558.82,1431.65
  Top Layer w20: v1(1669.56,1440.47) 1742.26,1440.47 1747.29,1445.39 R33.2@1750,1448.36 ; R33.2@1753.77,1444.59 1757.89,1440.47 R4.1@2550,1440.47 ; R4.1@2558.82,1431.65 Q2.2@2643.85,1431.65
  Layer 2 w10: v1(1669.56,1440.47) v1@1669.78,1440.69 ; v1@1669.78,1939.78 v1(1670,1940)
  Layer 2 w20: v1@1669.78,1440.69 v1@1669.78,1939.78
INT_5V: B1.9 R10.2 | length 2695.2
  Top Layer w10: v1(1321.67,2020) R10.2@1400.95,2020 ; v1(3200.16,1302.91) 3225.32,1328.07 B1.9@3225.32,1429.06
  Layer 2 w10: v1(1321.67,2020) 1321.67,1628.33 1736.93,1213.07 3110.31,1213.07 v1(3200.16,1302.91)
LPUART1_RX: J9.2 U1.17 | length 330.6
  Top Layer w10: U1.17@2116.14,2194.88 2207.34,2194.88 2275,2262.54 J9.2@2275,2406.3
LPUART1_TX: J9.1 U1.14 | length 483.7
  Top Layer w10: U1.14@2194.88,2076.77 2234.8,2076.77 2256.58,2055 2278.19,2055 2375,2151.81 J9.1@2375,2406.3
NetB1_8: B1.8 R3.1 | length 1265.7
  Top Layer w10: v1(3180.16,1369.84) 3205.63,1395.31 B1.8@3205.63,1429.06 ; v1(3205,2115) R3.1@3628.16,2115
  Layer 2 w10: v1(3180.16,1369.84) 3159.21,1390.79 3159.21,2069.21 v1(3205,2115)
NetB1_12: B1.12 C1.1 | length 194.9
  Top Layer w10: B1.12@3284.37,1429.06 3284.37,1370.63 3345.16,1309.84 C1.1@3395.63,1309.84
NetB1_13: B1.13 R6.2 | length 129.6
  Top Layer w10: B1.13@3310.94,1455.63 3310.94,1434.06 3346.3,1398.71 3384.68,1398.71 R6.2@3398.54,1384.84
NetB1_15: B1.15 C4.2 | length 103.8
  Top Layer w10: B1.15@3310.94,1495 3340,1495 3360.47,1474.53 3385.47,1474.53 C4.2@3400.16,1459.84
NetB1_20: B1.20 C5.1 | length 94.4
  Top Layer w10: B1.20@3264.68,1580.63 3264.68,1674.37 C5.1@3265.16,1674.84
NetB1_22: B1.22 R12.1 | length 1518.9
  Top Layer w10: B1.22@3225.32,1580.63 3225.32,1604.69 3170.16,1659.84 3062.12,1659.84 2980.16,1577.88 2980.16,747.48 3047.63,680.01 3307.59,680.01 R12.1@3312.6,675
NetC16_1: C16.1 U2.4 | length 108.8
  Top Layer w20: C16.1@234.14,1980.35 U2.4@342.92,1980.35
NetC16_2: C16.2 U2.2 | length 108.8
  Top Layer w20: C16.2@234.14,2080.35 U2.2@342.92,2080.35
NetC20_1: C20.1 U4.7 | length 89.9
  Top Layer w10: U4.7@1063.95,957.98 1100.47,957.98 1121.2,978.72 1144.83,978.72 C20.1@1145.11,979
NetC21_1: C21.1 U5.7 | length 92.3
  Top Layer w10: U5.7@1822.68,957.61 1886.3,957.61 1904.5,975.81 C21.1@1904.5,978.76
NetC22_1: C22.1 U5.6 | length 89.8
  Top Layer w10: U5.6@1822.68,937.92 1864.15,937.92 1897.61,904.46 C22.1@1898.6,904.46
NetC22_2: C22.2 L1.1 U5.5 | length 279.6
  Top Layer w10: U5.5@1822.68,918.24 1823.58,917.33 1832.53,917.33 1849.37,900.49 1849.37,845.48 1873.9,820.96 L1.1@1898.58,820.96
  Top Layer w20: L1.1@1898.58,820.96 1938.12,820.96 1957.65,840.48 C22.2@1957.65,904.46
NetC23_2: C23.2 L2.1 U4.5 | length 281.8
  Top Layer w10: U4.5@1063.87,918.47 1067.09,918.47 1067.99,917.57 1067.99,845.39 1092.52,820.87 L2.1@1141.73,820.87
  Top Layer w20: L2.1@1141.73,820.87 1171.73,820.87 1191.26,840.39 C23.2@1191.26,904
NetD1_1: D1.1 R3.2 | length 184.4
  Top Layer w10: R3.2@3705,2115 3719.99,2130 D1.1@3719.99,2293.17
NetD2_1: D2.1 R25.1 | length 129
  Top Layer w10: R25.1@3718.23,421.73 3720,423.5 D2.1@3720,550
NetD4_2: D4.2 Q5.2 | length 100
  Top Layer w10: D4.2@2690.12,1839.89 Q5.2@2690.12,1939.89
NetQ1_5-6-7-8: Q1.5-6-7-8 Q4.5-6-7-8 | length 179.5
  Top Layer w50: Q4.5-6-7-8@3415.16,949.84 3416.42,951.11 3592.33,951.11 Q1.5-6-7-8@3593.59,952.37
NetQ5_1: Q5.1 R31.2 | length 100
  Top Layer w10: R31.2@2618.07,1839.89 Q5.1@2618.07,1939.89
NetQ5_3: Q5.3 R30.1 | length 124.8
  Top Layer w10: R30.1@2529.31,2016.8 Q5.3@2654.09,2016.8
NetQ6_1: Q6.1 U1.43 | length 2915.7
  Top Layer w10: v1(225,475) 225,452.71 233.81,443.9 Q6.1@318.9,443.9 ; v1(1250,1950) 1550,1950 1585,1915 1689.43,1915 1693.72,1919.29 U1.43@1742.13,1919.29
  Layer 2 w10: v1(225,475) 225,450 300,375 550.05,375 1300,1124.95 1300,1450 1250,1500 v1(1250,1950)
NetR9_1: R9.1 R10.1 U1.38 | length 300.9
  Top Layer w10: R10.1@1460,2020 R9.1@1540,2020 1541.38,2018.62 1592.96,2018.62 1614.48,2040.15 1657.78,2040.15 1680.21,2017.72 U1.38@1742.13,2017.72
NetR14_1: R14.1 VR1.2 | length 505.7
  Top Layer w10: R14.1@647.21,1467.99 R14.1@654.22,1475
  Top Layer w20: R14.1@654.22,1475 VR1.2@1150,1475
NetR16_2: R16.2 VR1.1 | length 441.7
  Top Layer w20: R16.2@647.21,1381.09 691.11,1425 1000,1425 VR1.1@1050,1375
NetR17_1: R17.1 R18.2 | length 67.9
  Top Layer w20: R18.2@628.5,1245.73 629.82,1245.73 632.79,1248.7 R17.1@632.79,1311.06
NetR19_1: R19.1 R20.2 | length 88.7
  Top Layer w20: R19.1@983.71,1151.04 R19.1@985.35,1149.41 R20.2@1071.7,1149.41
NetR20_1: R20.1 U4.1 | length 147.7
  Top Layer w10: U4.1@1005.6,977.53 1005.6,1030.02 1060.72,1085.14 1060.72,1088.16 1068.68,1096.13 R20.1@1071.7,1096.13
NetR21_1: R21.1 R22.2 | length 81.1
  Top Layer w20: R21.1@1746.34,1148.69 R22.2@1827.4,1148.69
NetR22_1: R22.1 U5.1 | length 146
  Top Layer w10: U5.1@1764.41,977.29 1764.41,1035.43 1824.38,1095.4 R22.1@1827.4,1095.4
NetR24_1: R24.1 R26.1 U5.8 | length 469.8
  Top Layer w10: U5.8@1822.68,977.29 1823.58,978.2 1831.62,978.2 1877.04,1023.62 2018.2,1023.62 2063.54,978.28 R24.1@2063.54,860.41
  Top Layer w20: R26.1@2063.54,787.35 R24.1@2063.54,860.41
NetR27_1: R27.1 R29.1 U4.8 | length 566.6
  Top Layer w10: U4.8@1064.1,977.52 1087.25,977.52 1138.73,1029
  Top Layer w20: 1138.73,1029 1231.16,1029 1288.73,971.43 R29.1@1288.73,744.59 R27.1@1358.73,744.59
NetU1_39: U1.39 U5.2 | length 1248.9
  Top Layer w10: v1(1638.98,2015.15) 1640.1,2015.15 1657.22,1998.03 U1.39@1742.13,1998.03 ; v1(1714.57,957.61) U5.2@1764.41,957.61
  Bottom Layer w10: v1(1638.98,2015.15) 1638.98,1033.2 v1(1714.57,957.61)
NRST: C6.2 J3.10 U1.7 | length 1854.8
  Top Layer w10: J3.10@1868.5,3174.61 1868.5,3198.5 2000,3330 2140,3330 2200,3270 v1(2200,2920)
  Top Layer w12: U1.7@2194.88,1938.98 C6.2@2258.5,1938.98 2259.25,1939.72 2259.25,1989.25 v1(2260,1990)
  Bottom Layer w10: v1(2200,2920) 2200,2050 v1(2260,1990)
OPA_1+: R16.1 R17.2 U3.3 | length 152.5
  Top Layer w20: U3.3@505.91,1382.36 506.54,1381.73 587.52,1381.73 R17.2@587.52,1311.06
OPA_1-: R13.1 R15.2 U3.4 | length 241.6
  Top Layer w10: R15.2@356.3,1463.07 366.3,1453.07 484.32,1453.07 499.1,1467.84 499.1,1477.91 U3.4@505.91,1484.72
  Top Layer w12: U3.4@505.91,1484.72 R13.1@505.91,1553.54
OPA_1Out: R15.1 R23.2 U3.1 | length 489.1
  Top Layer w20: R15.1@356.3,1404.01 419.29,1404.01 U3.1@431.1,1392.2 ; R23.2@431.1,972.91 U3.1@431.1,1382.36
OPA_2-: R23.1 R28.1 U6.4 | length 350.7
  Top Layer w10: R28.1@262.76,740.2 262.76,739.26 278.59,723.43 404.53,723.43 431.1,750 U6.4@431.1,759.84
  Top Layer w20: U6.4@431.1,759.84 R23.1@431.1,913.86
OPA_2Out: Q6.3 R28.2 U6.1 | length 239.2
  Top Layer w20: R28.2@262.76,677.12 262.76,674.21 279.49,657.48 U6.1@356.3,657.48 ; Q6.3@356.3,522.64 U6.1@356.3,658.46
PSU_OUT: C15.1 D3.1 J8.1 Q4.1 Q4.2 Q4.3 R12.2 R25.2 | length 110.9
  Top Layer w10: J8.1@3385.83,193.36 J8.1@3464.27,271.81
  other v2: 3385.83,208.36
PWREN: B1.23 Q1.4 Q4.4 | length 1628.8
  Top Layer w10: B1.23@3205.63,1580.63 3204.73,1581.54 3204.73,1596.66 3156.54,1644.84 3068.34,1644.84 3005.16,1581.66 3005.16,1141.79 3067.1,1079.84 3253.23,1079.84 3259.45,1086.06 v1(3448.28,1086.06) 3505.44,1028.9 Q1.4@3541.77,1028.9 ; Q4.4@3466.98,873.32 3503.66,873.32 v1(3526.97,850)
  Bottom Layer w10: v1(3448.28,1086.06) 3526.97,1007.37 v1(3526.97,850)
SCL_5V: B1.5 Q3.3 R7.1 | length 524.8
  Top Layer w10: v1(3080.16,1444.84) 3110.63,1475.31 B1.5@3159.37,1475.31
  Top Layer w20: Q3.3@2715.52,1280 R7.1@2803.85,1280 v1(2870,1280)
  Layer 2 w20: v1(2870,1280) 3034.84,1444.84 v1(3080.16,1444.84)
SDA_5V: B1.4 Q2.3 R5.1 | length 454.6
  Top Layer w10: R5.1@2803.85,1469.06 R5.1@2804.8,1470 ; v1(3080.16,1494.84) 3080.24,1494.92 3159.29,1494.92 B1.4@3159.37,1495
  Top Layer w20: Q2.3@2715.52,1469.06 R5.1@2803.85,1469.06 ; R5.1@2804.8,1470 v1(2870,1470)
  Layer 2 w20: v1(2870,1470) 2894.84,1494.84 v1(3080.16,1494.84)
SPI_MISO: J2.05 U1.20 | length 1875.9
  Top Layer w10: U1.20@2057.09,2194.88 2057.09,2456.73 v1(2100.39,2500.04)
  Layer 2 w20: J2.05@2018.5,3740.16 1714.57,3436.22 1714.57,2839.78 2054.31,2500.04 v1(2100.39,2500.04)
SPI_MOSI: J2.04 U1.21 | length 1895.4
  Top Layer w10: U1.21@2037.4,2194.88 2037.4,2483.77 v1(2100.39,2546.76)
  Layer 2 w20: v1(2100.39,2546.76) 2053.04,2546.76 1751.75,2848.05 1751.75,3373.41 J2.04@2118.5,3740.16
SPI_SCK: J2.06 U1.19 | length 1865.8
  Top Layer w10: U1.19@2076.77,2194.88 2076.77,2233.34 2072.09,2238.02 2072.09,2421.69 v1(2100.39,2450)
  Layer 2 w20: J2.06@1918.5,3740.16 1670.51,3492.17 1670.51,2835.45 2055.97,2450 v1(2100.39,2450)
SWCLK: J3.4 U1.50 | length 1605.8
  Top Layer w10: v1(1820,1680) 1840.55,1700.55 U1.50@1840.55,1742.13 ; v1(1975,2920) 1975,3060 1980.86,3065.86 1980.86,3081.26 2014.49,3114.89 2018.5,3118.92 J3.4@2018.5,3124.61
  Bottom Layer w10: v1(1820,1680) 1935,1795 1935,2107.12 1945,2117.12 1945,2137.83 1935,2147.83 1935,2317.66 1975,2357.66 v1(1975,2920)
SWDIO: J3.2 U1.49 | length 1582.3
  Top Layer w10: v1(1780,1680) 1781.91,1681.91 1781.91,1685.46 1820.87,1724.41 U1.49@1820.87,1742.13 ; J3.2@1918.5,3124.61 1918.5,3116.4 1920,3114.91 v1(1920,2920)
  Bottom Layer w10: v1(1780,1680) 1895,1795 1895,2895 v1(1920,2920)
SWO: J3.6 U1.56 | length 1709.9
  Top Layer w10: v1(1958.19,1680.24) 1958.43,1680.47 1958.43,1741.89 U1.56@1958.66,1742.13 ; J3.6@2068.5,3174.61 2074.19,3174.61 2078.21,3170.59 2088.69,3170.59 2112.02,3147.26 2129.68,3147.26 2153,3123.94 2153,3062.6 2165.25,3050.35 2165.25,3029.64 2153,3017.39 2153,2943 v1(2130,2920)
  Bottom Layer w10: v1(1958.19,1680.24) 1960.24,1680.24 2055.89,1775.89 2067.13,1775.89 2081.77,1790.54 2081.77,1801.77 2130,1850 v1(2130,2920)
User_LED: R31.1 U1.2 | length 376.1
  Top Layer w10: U1.2@2194.88,1840.55 2570.08,1840.55 R31.1@2570.74,1839.89
VBUS: B1.1 J1.A4-B9 J1.B4-A9 R11.1 | length 864.9
  Top Layer w10: v1(3110.16,1589.84) 3112.07,1587.93 3116.64,1587.93 3150.51,1554.06 B1.1@3159.37,1554.06
  Bottom Layer w25: v1(3110.16,1589.84) 3170.16,1649.84 3595.58,1649.84 v1(3596.74,1651) v1(3621.74,1651) v1(3646.74,1651) v1(3646.74,1462.03) ; v1@3596.74,1461 v1@3646.74,1461
  other v1: 3596.74,1462.03 3621.74,1462.03
VBUS_SNS: B1.24 C12.1 Q1.1 Q1.2 Q1.3 R11.2 U4.3 U5.3 | length 4217.5
  Top Layer w10: 3035.16,1579.84 3085.16,1629.84 3115.16,1629.84 3164.37,1580.63 B1.24@3185.94,1580.63
  Top Layer w12: v1(952.46,901.21) 953.99,902.74 953.99,913.2 978.95,938.16 U4.3@1005.6,938.16 ; v1(1703.11,901.21) 1739.82,937.92 U5.3@1764.41,937.92
  Top Layer w25: 3035.16,1579.84 3035.16,1349.84 3221.5,1163.51 R11.2@3610.16,1163.51 v1(3723.15,1163.51)
  Bottom Layer w25: v1(952.46,901.21) v1(1703.11,901.21) 1803.09,901.21 1975.54,1073.66 2820.87,1073.66 2910.72,1163.51 v1(3723.15,1163.51)
WAV_JACK: J4.1 Q6.2 | length 132.5
  Top Layer w20: Q6.2@393.7,443.9 393.7,445.87 405.73,457.9 J4.1@519.29,457.9
pads on no net: B1.2 B1.6 B1.7 B1.10 B1.11 B1.14 B1.21 J1. J1.A8 J1.B8 J2.07 J3. J3.7 J3.8 J3.9 J4.2 J4.3 U1.3 U1.4 U1.5 U1.6 U1.8 U1.9 U1.10 U1.11 U1.12 U1.13 U1.23 U1.24 U1.25 U1.26 U1.30 U1.33 U1.34 U1.35 U1.36 U1.37 U1.41 U1.44 U1.45 U1.46 U1.52 U1.53 U1.54 U1.55 U1.57 U1.58 U1.59 U1.60 U2.1 U2.7 U7.3 U7.5 VR1.3

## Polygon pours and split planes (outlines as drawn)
GND on Top Layer "GND_L01_P037" (solid, pour order 37): 859,1753.73 1531.37,1081.36 cw(c1525.01,1075.01) 1534,1075 1534,39.37 2307.12,39.37 2307.12,391.12 cw(c2316.12,391.12) 2309.76,397.49 2893.64,981.36 2966,1053.73 2966,1750 cw(c2975,1750) 2968.64,1756.36 3165.36,1953.09 cw(c3171.73,1946.73) 3171.73,1955.73 3897.64,1955.73 3897.64,3897.64 859,3897.64
GND on Top Layer "GND_L01_P038" (solid, pour order 38): 2325.12,39.37 2325.12,387.39 2906.36,968.64 2981.36,1043.64 ccw(c2975,1050) 2984,1050 2984,1746.27 3175.46,1937.73 3897.64,1937.73 3897.64,39.37
GND on Top Layer "GND_L01_P036" (solid, pour order 36): 39.37,39.37 1516,39.37 1516,1071.27 843.64,1743.64 cw(c850,1750) 841,1750 841,3897.64 39.37,3897.64
GND on Top Layer "GND_L01_P045" (solid, pour order 45): 1025,3375 675,3375 675,3897.64 1025,3897.64
GND on Top Layer "GND_L01_P044" (solid, pour order 44): 3460.83,2200 3460.83,1850 3250,1850 3250,2200
PSU_OUT on Top Layer "PSU_OUT_L01_P034" (solid, pour order 34): 3624.52,100 3624.52,800 3453.43,800 3453.43,897.01 3359.39,897.01 3359.39,100
VBUS_SNS on Top Layer "VBUS_SNS_L01_P033" (solid, pour order 33): 3465.16,1204.63 3465.16,1099.84 3510.16,1099.84 3523.94,1086.06 3523.94,1009.84 3660.16,1009.84 3660.16,1039.84 3660.16,1199.46
VBUS on Top Layer "VBUS_L01_P032" (solid, pour order 32): 3666.18,1447.03 3665.16,1446 3665.16,1214.84 3565.16,1214.84 3565.16,1477.03 3721.73,1477.03 3721.73,1447.03
VBUS on Top Layer "VBUS_L01_P031" (solid, pour order 31): 3576.73,1674.84 3576.73,1629.84 3721.73,1629.84 3721.73,1674.84
3VO_JACK on Top Layer "3VO_JACK_L01_P030" (solid, pour order 30): 1805.58,719.09 1805.58,236.22 1985.58,236.22 1985.58,639.09 1985.58,719.09
5VO on Top Layer "5VO_L01_P029" (solid, pour order 29): 1048.73,719 1048.73,203.05 1228.73,203.05 1228.73,639 1228.73,719
+5 on Layer 1 "+5_L02_P035" (solid, pour order 35): 39.37,39.37 39.37,3897.64 3897.64,3897.64 3897.64,39.37
3V3 on Layer 1 "3V3_L02_P028" (solid, pour order 28): 1360,2850 1360,1350 2400,1350 2400,2850
GND on Layer 2 "GND_L03_P039" (solid, pour order 39): 859,1753.73 1531.37,1081.36 cw(c1525.01,1075.01) 1534,1075 1534,39.37 2307.12,39.37 2307.12,391.12 cw(c2316.12,391.12) 2309.76,397.49 2893.64,981.36 2966,1053.73 2966,1750 cw(c2975,1750) 2968.64,1756.36 3165.36,1953.09 cw(c3171.73,1946.73) 3171.73,1955.73 3897.64,1955.73 3897.64,3897.64 859,3897.64
GND on Layer 2 "GND_L03_P042" (solid, pour order 42): 1025,3375 675,3375 675,3897.64 1025,3897.64
GND on Layer 2 "GND_L03_P043" (solid, pour order 43): 3460.83,2200 3460.83,1850 3250,1850 3250,2200
GND on Layer 2 "GND_L03_P041" (solid, pour order 41): 39.37,39.37 1516,39.37 1516,1071.27 843.64,1743.64 cw(c850,1750) 841,1750 841,3897.64 39.37,3897.64
GND on Layer 2 "GND_L03_P040" (solid, pour order 40): 2325.12,39.37 2325.12,387.39 2906.36,968.64 2981.36,1043.64 ccw(c2975,1050) 2984,1050 2984,1746.27 3175.46,1937.73 3897.64,1937.73 3897.64,39.37

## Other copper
Layer 1:
  pour cut-out: 2400,2900 2400,1300 2450,1300 2450,2900
  pour cut-out: 1325,2900 1325,1300 1375,1300 1375,2900
  pour cut-out: 1325,2900 1325,2850 2450,2850 2450,2900

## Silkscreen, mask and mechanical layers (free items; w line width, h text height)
Top Overlay:
  drawing of 37 lines, arcs and shapes, not listed
  text "EECS473 Group 14 F25" at 189.37,3237.51 h60
  text "PSU / Waveform Module" at 185,3135 h60
  text "REV2" at 185,3035 h60
  text "3.3V Supply" at 1114.86,2749.61 h40
  text "UARX" at 2295.35,2493.77 h60 r90
  text "UATX" at 2408.5,2493.77 h60 r90
  text "-5V Supply" at 240.57,2348.88 h40
  text "Debug LED" at 2454.46,2188.68 h40
  text "Wave Gen Stage 1" at 170.81,1117.23 h40 r90
  text "Fixed 5V Output" at 813.33,569.12 h40 r90
  text "Wave Gen Stage 2" at 170.81,433.21 h40 r90
  text "Fixed 3.3V Output" at 1588.13,402.58 h40 r90
  text "USB-C Power Delivery" at 2888.33,393.07 h40 r90
  text "5V" at 1365.27,125.59 h40 r90
  text "PSU_OUT" at 3014.83,49.37 h40 r90
Board:
  circle w10: c196.85,3740.16 r70.87
  circle w10: c3740.16,196.85 r70.87
  circle w10: c3740.16,3740.16 r70.87
  circle w10: c197.56,196.07 r70.87
  lines w10: 0,70.87 ccw(c70.87,70.87) 70.87,0 3866.14,0 ccw(c3866.14,70.87) 3937.01,70.87 3937.01,3866.14 ccw(c3866.14,3866.14) 3866.14,3937.01 70.87,3937.01 ccw(c70.87,3866.14) 0,3866.14 0,70.87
